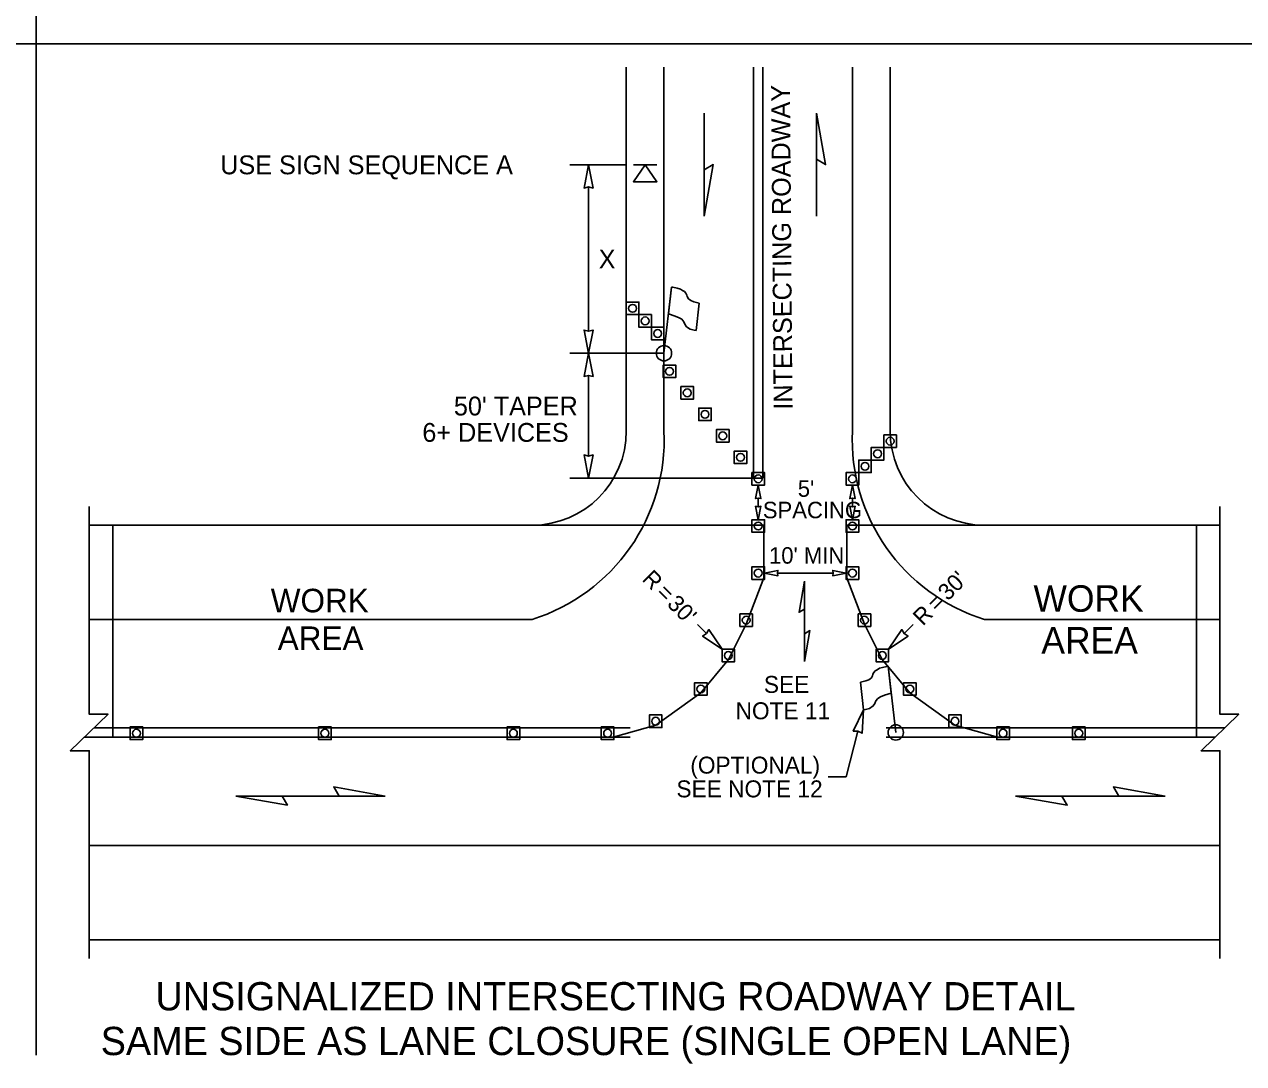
# Model space of a CAD drawing. Extents: x 99999.1 to 100095.7, y 99995 to 100010.7.
# Drawn here: x 100025.2 to 100030.38, y 100001.65 to 100006.06 of the extents above; entities that cross this region are included whole.
import ezdxf

# ---------------------------------------------------------------- set-up
doc = ezdxf.new("R2010")
doc.units = 0
for name, color, linetype in [('RD_ED_ShoulderPavedEdge', 7, 'Continuous'), ('RD_MK_LineDblYellowCenter', 7, 'Continuous'), ('RD_MK_LineEdgeWhite', 7, 'Continuous'), ('RD_MK_LineStop', 7, 'Continuous'), ('SH_DE_DetailBody1Text', 7, 'Continuous'), ('SH_DE_DetailHeading2Text', 7, 'Continuous'), ('TR_WZ_FlaggingStation', 7, 'Continuous'), ('TR_WZ_PortableSignMountBlk-Org', 7, 'Continuous'), ('TR_WZ_TrafficCone', 7, 'Continuous'), ('TR_WZ_WorkAreaLabel', 7, 'Continuous'), ('TR_WZ_WorkZoneDetails', 7, 'Continuous'), ('TR_WZ_WorkZoneTextCurrent', 7, 'Continuous')]:
    doc.layers.add(name, color=color, linetype=linetype)

msp = doc.modelspace()

# ---------------------------------------------------------------- linework, layer by layer
at = {"layer": 'RD_ED_ShoulderPavedEdge'}
for p, q in [((100025.475, 100003.9359), (100027.355, 100003.9359)), ((100029.275, 100003.9359), (100030.275, 100003.9359)), ((100025.475, 100002.1759), (100030.275, 100002.1759))]:
    msp.add_line(p, q, dxfattribs=at)
for points in [[(100027.755, 100005.8804), (100027.755, 100004.3359)], [(100028.875, 100005.8804), (100028.875, 100004.3359)]]:
    msp.add_lwpolyline(points, dxfattribs=at)
for centre, start, end in [((100027.355, 100004.3359), 270, 0), ((100029.275, 100004.3359), 180, 270)]:
    msp.add_arc(centre, 0.4, start, end, dxfattribs=at)
at = {"layer": 'RD_MK_LineDblYellowCenter'}
for p, q in [((100028.295, 100005.8804), (100028.295, 100004.1359)), ((100028.335, 100005.8804), (100028.335, 100004.1359)), ((100025.4957, 100003.0759), (100027.7712, 100003.0759)), ((100028.8588, 100003.0759), (100030.2957, 100003.0759)), ((100025.4543, 100003.0359), (100027.7712, 100003.0359)), ((100028.8588, 100003.0359), (100030.2543, 100003.0359))]:
    msp.add_line(p, q, dxfattribs=at)
at = {"layer": 'RD_MK_LineEdgeWhite'}
for p, q in [((100027.915, 100004.3359), (100027.915, 100005.8804)), ((100028.715, 100004.3359), (100028.715, 100005.8804)), ((100025.475, 100003.5359), (100027.355, 100003.5359)), ((100029.275, 100003.5359), (100030.275, 100003.5359)), ((100025.475, 100002.5759), (100030.275, 100002.5759))]:
    msp.add_line(p, q, dxfattribs=at)
for centre, start, end in [((100027.1158, 100004.2993), 287.3948, 2.6212), ((100029.5142, 100004.2993), 177.3788, 252.6052)]:
    msp.add_arc(centre, 0.8, start, end, dxfattribs=at)
at = {"layer": 'RD_MK_LineStop'}
msp.add_line((100027.899, 100004.1359), (100028.335, 100004.1359), dxfattribs=at)
at = {"layer": 'TR_WZ_FlaggingStation'}
for p, q in [((100027.915, 100004.6659), (100027.9471, 100004.9468)), ((100027.934, 100004.8328), (100027.9471, 100004.9471)), ((100028.065, 100004.8793), (100028.0517, 100004.7621)), ((100027.934, 100004.8328), (100027.934, 100004.8328)), ((100028.8797, 100003.2228), (100028.8667, 100003.3371)), ((100028.8988, 100003.0559), (100028.8667, 100003.3368)), ((100028.7487, 100003.2693), (100028.762, 100003.1521)), ((100028.8797, 100003.2228), (100028.8797, 100003.2228))]:
    msp.add_line(p, q, dxfattribs=at)
for points in [[(100027.9471, 100004.9471), (100027.9528, 100004.9459), (100027.9707, 100004.9424), (100027.9845, 100004.9383), (100027.9942, 100004.9322), (100028.0027, 100004.9275), (100028.0084, 100004.9206), (100028.0126, 100004.9128), (100028.0131, 100004.9066), (100028.0185, 100004.8974), (100028.0293, 100004.8899), (100028.0417, 100004.8847), (100028.065, 100004.8793)], [(100028.0517, 100004.7621), (100028.0436, 100004.7636), (100028.0259, 100004.7682), (100028.0103, 100004.7787), (100028.0037, 100004.7893), (100027.9998, 100004.7996), (100027.9907, 100004.8105), (100027.9798, 100004.8167), (100027.9624, 100004.8238), (100027.934, 100004.8328)], [(100028.8667, 100003.3371), (100028.8609, 100003.3359), (100028.8431, 100003.3324), (100028.8293, 100003.3283), (100028.8196, 100003.3222), (100028.8111, 100003.3175), (100028.8054, 100003.3106), (100028.8012, 100003.3028), (100028.8006, 100003.2966), (100028.7953, 100003.2874), (100028.7845, 100003.2799), (100028.7721, 100003.2747), (100028.7487, 100003.2693)], [(100028.762, 100003.1521), (100028.7702, 100003.1536), (100028.7879, 100003.1582), (100028.8035, 100003.1687), (100028.81, 100003.1793), (100028.814, 100003.1896), (100028.823, 100003.2005), (100028.834, 100003.2067), (100028.8514, 100003.2138), (100028.8797, 100003.2228)]]:
    msp.add_lwpolyline(points, dxfattribs=at)
for centre in [(100027.915, 100004.6659), (100028.8988, 100003.0559)]:
    msp.add_circle(centre, 0.0325, dxfattribs=at)
at = {"layer": 'TR_WZ_PortableSignMountBlk-Org'}
msp.add_line((100027.785, 100005.4659), (100027.885, 100005.4659), dxfattribs=at)
msp.add_lwpolyline([(100027.8349, 100005.4659), (100027.885, 100005.3941), (100027.785, 100005.3941)], close=True, dxfattribs=at)
at = {"layer": 'TR_WZ_TrafficCone'}
for points in [[(100027.8083, 100004.8833), (100027.8083, 100004.8299), (100027.755, 100004.8299), (100027.755, 100004.8833), (100027.8083, 100004.8833)], [(100027.755, 100004.8833), (100027.755, 100004.8299), (100027.8083, 100004.8299), (100027.8083, 100004.8833), (100027.755, 100004.8833)], [(100027.8617, 100004.8299), (100027.8617, 100004.7766), (100027.8083, 100004.7766), (100027.8083, 100004.8299), (100027.8617, 100004.8299)], [(100027.8083, 100004.8299), (100027.8083, 100004.7766), (100027.8617, 100004.7766), (100027.8617, 100004.8299), (100027.8083, 100004.8299)], [(100027.915, 100004.7766), (100027.915, 100004.7233), (100027.8617, 100004.7233), (100027.8617, 100004.7766), (100027.915, 100004.7766)], [(100027.8617, 100004.7766), (100027.8617, 100004.7233), (100027.915, 100004.7233), (100027.915, 100004.7766), (100027.8617, 100004.7766)], [(100027.9117, 100004.6159), (100027.965, 100004.6159), (100027.965, 100004.5626), (100027.9117, 100004.5626), (100027.9117, 100004.6159)], [(100027.9117, 100004.5626), (100027.965, 100004.5626), (100027.965, 100004.6159), (100027.9117, 100004.6159), (100027.9117, 100004.5626)], [(100027.987, 100004.5246), (100028.0404, 100004.5246), (100028.0404, 100004.4712), (100027.987, 100004.4712), (100027.987, 100004.5246)], [(100027.987, 100004.4712), (100028.0404, 100004.4712), (100028.0404, 100004.5246), (100027.987, 100004.5246), (100027.987, 100004.4712)], [(100028.0624, 100004.4332), (100028.1157, 100004.4332), (100028.1157, 100004.3799), (100028.0624, 100004.3799), (100028.0624, 100004.4332)], [(100028.0624, 100004.3799), (100028.1157, 100004.3799), (100028.1157, 100004.4332), (100028.0624, 100004.4332), (100028.0624, 100004.3799)], [(100028.1377, 100004.3419), (100028.191, 100004.3419), (100028.191, 100004.2886), (100028.1377, 100004.2886), (100028.1377, 100004.3419)], [(100028.1377, 100004.2886), (100028.191, 100004.2886), (100028.191, 100004.3419), (100028.1377, 100004.3419), (100028.1377, 100004.2886)], [(100028.9016, 100004.3192), (100028.8483, 100004.3192), (100028.8483, 100004.2659), (100028.9016, 100004.2659), (100028.9016, 100004.3192)], [(100028.9016, 100004.2659), (100028.8483, 100004.2659), (100028.8483, 100004.3192), (100028.9016, 100004.3192), (100028.9016, 100004.2659)], [(100028.213, 100004.2506), (100028.2664, 100004.2506), (100028.2664, 100004.1972), (100028.213, 100004.1972), (100028.213, 100004.2506)], [(100028.213, 100004.1972), (100028.2664, 100004.1972), (100028.2664, 100004.2506), (100028.213, 100004.2506), (100028.213, 100004.1972)], [(100028.8483, 100004.2659), (100028.795, 100004.2659), (100028.795, 100004.2126), (100028.8483, 100004.2126), (100028.8483, 100004.2659)], [(100028.8483, 100004.2126), (100028.795, 100004.2126), (100028.795, 100004.2659), (100028.8483, 100004.2659), (100028.8483, 100004.2126)], [(100028.795, 100004.2126), (100028.7416, 100004.2126), (100028.7416, 100004.1592), (100028.795, 100004.1592), (100028.795, 100004.2126)], [(100028.795, 100004.1592), (100028.7416, 100004.1592), (100028.7416, 100004.2126), (100028.795, 100004.2126), (100028.795, 100004.1592)], [(100028.2884, 100004.1592), (100028.3417, 100004.1592), (100028.3417, 100004.1059), (100028.2884, 100004.1059), (100028.2884, 100004.1592)], [(100028.2884, 100004.1059), (100028.3417, 100004.1059), (100028.3417, 100004.1592), (100028.2884, 100004.1592), (100028.2884, 100004.1059)], [(100028.7416, 100004.1592), (100028.6883, 100004.1592), (100028.6883, 100004.1059), (100028.7416, 100004.1059), (100028.7416, 100004.1592)], [(100028.7416, 100004.1059), (100028.6883, 100004.1059), (100028.6883, 100004.1592), (100028.7416, 100004.1592), (100028.7416, 100004.1059)], [(100028.2884, 100003.9592), (100028.3417, 100003.9592), (100028.3417, 100003.9059), (100028.2884, 100003.9059), (100028.2884, 100003.9592)], [(100028.2884, 100003.9059), (100028.3417, 100003.9059), (100028.3417, 100003.9592), (100028.2884, 100003.9592), (100028.2884, 100003.9059)], [(100028.7416, 100003.9592), (100028.6883, 100003.9592), (100028.6883, 100003.9059), (100028.7416, 100003.9059), (100028.7416, 100003.9592)], [(100028.7416, 100003.9059), (100028.6883, 100003.9059), (100028.6883, 100003.9592), (100028.7416, 100003.9592), (100028.7416, 100003.9059)], [(100028.2884, 100003.7592), (100028.3417, 100003.7592), (100028.3417, 100003.7059), (100028.2884, 100003.7059), (100028.2884, 100003.7592)], [(100028.2884, 100003.7059), (100028.3417, 100003.7059), (100028.3417, 100003.7592), (100028.2884, 100003.7592), (100028.2884, 100003.7059)], [(100028.7416, 100003.7592), (100028.6883, 100003.7592), (100028.6883, 100003.7059), (100028.7416, 100003.7059), (100028.7416, 100003.7592)], [(100028.7416, 100003.7059), (100028.6883, 100003.7059), (100028.6883, 100003.7592), (100028.7416, 100003.7592), (100028.7416, 100003.7059)], [(100028.2373, 100003.5592), (100028.2907, 100003.5592), (100028.2907, 100003.5059), (100028.2373, 100003.5059), (100028.2373, 100003.5592)], [(100028.2373, 100003.5059), (100028.2907, 100003.5059), (100028.2907, 100003.5592), (100028.2373, 100003.5592), (100028.2373, 100003.5059)], [(100028.7927, 100003.5592), (100028.7393, 100003.5592), (100028.7393, 100003.5059), (100028.7927, 100003.5059), (100028.7927, 100003.5592)], [(100028.7927, 100003.5059), (100028.7393, 100003.5059), (100028.7393, 100003.5592), (100028.7927, 100003.5592), (100028.7927, 100003.5059)], [(100028.1617, 100003.4093), (100028.215, 100003.4093), (100028.215, 100003.3559), (100028.1617, 100003.3559), (100028.1617, 100003.4093)], [(100028.1617, 100003.3559), (100028.215, 100003.3559), (100028.215, 100003.4093), (100028.1617, 100003.4093), (100028.1617, 100003.3559)], [(100028.8683, 100003.4093), (100028.815, 100003.4093), (100028.815, 100003.3559), (100028.8683, 100003.3559), (100028.8683, 100003.4093)], [(100028.8683, 100003.3559), (100028.815, 100003.3559), (100028.815, 100003.4093), (100028.8683, 100003.4093), (100028.8683, 100003.3559)], [(100028.0447, 100003.267), (100028.0981, 100003.267), (100028.0981, 100003.2136), (100028.0447, 100003.2136), (100028.0447, 100003.267)], [(100028.0447, 100003.2136), (100028.0981, 100003.2136), (100028.0981, 100003.267), (100028.0447, 100003.267), (100028.0447, 100003.2136)], [(100028.9853, 100003.267), (100028.9319, 100003.267), (100028.9319, 100003.2136), (100028.9853, 100003.2136), (100028.9853, 100003.267)], [(100028.9853, 100003.2136), (100028.9319, 100003.2136), (100028.9319, 100003.267), (100028.9853, 100003.267), (100028.9853, 100003.2136)], [(100027.853, 100003.1302), (100027.9064, 100003.1302), (100027.9064, 100003.0768), (100027.853, 100003.0768), (100027.853, 100003.1302)], [(100027.853, 100003.0768), (100027.9064, 100003.0768), (100027.9064, 100003.1302), (100027.853, 100003.1302), (100027.853, 100003.0768)], [(100029.177, 100003.1302), (100029.1236, 100003.1302), (100029.1236, 100003.0768), (100029.177, 100003.0768), (100029.177, 100003.1302)], [(100029.177, 100003.0768), (100029.1236, 100003.0768), (100029.1236, 100003.1302), (100029.177, 100003.1302), (100029.177, 100003.0768)], [(100025.649, 100003.0792), (100025.7024, 100003.0792), (100025.7024, 100003.0259), (100025.649, 100003.0259), (100025.649, 100003.0792)], [(100025.649, 100003.0259), (100025.7024, 100003.0259), (100025.7024, 100003.0792), (100025.649, 100003.0792), (100025.649, 100003.0259)], [(100026.449, 100003.0792), (100026.5024, 100003.0792), (100026.5024, 100003.0259), (100026.449, 100003.0259), (100026.449, 100003.0792)], [(100026.449, 100003.0259), (100026.5024, 100003.0259), (100026.5024, 100003.0792), (100026.449, 100003.0792), (100026.449, 100003.0259)], [(100027.249, 100003.0792), (100027.3024, 100003.0792), (100027.3024, 100003.0259), (100027.249, 100003.0259), (100027.249, 100003.0792)], [(100027.249, 100003.0259), (100027.3024, 100003.0259), (100027.3024, 100003.0792), (100027.249, 100003.0792), (100027.249, 100003.0259)], [(100027.649, 100003.0792), (100027.7024, 100003.0792), (100027.7024, 100003.0259), (100027.649, 100003.0259), (100027.649, 100003.0792)], [(100027.649, 100003.0259), (100027.7024, 100003.0259), (100027.7024, 100003.0792), (100027.649, 100003.0792), (100027.649, 100003.0259)], [(100029.381, 100003.0792), (100029.3276, 100003.0792), (100029.3276, 100003.0259), (100029.381, 100003.0259), (100029.381, 100003.0792)], [(100029.381, 100003.0259), (100029.3276, 100003.0259), (100029.3276, 100003.0792), (100029.381, 100003.0792), (100029.381, 100003.0259)], [(100029.649, 100003.0792), (100029.7024, 100003.0792), (100029.7024, 100003.0259), (100029.649, 100003.0259), (100029.649, 100003.0792)], [(100029.649, 100003.0259), (100029.7024, 100003.0259), (100029.7024, 100003.0792), (100029.649, 100003.0792), (100029.649, 100003.0259)]]:
    msp.add_lwpolyline(points, dxfattribs=at)
for centre in [(100027.7817, 100004.8566), (100027.835, 100004.8033), (100027.8883, 100004.7499), (100027.9384, 100004.5892), (100028.0137, 100004.4979), (100028.089, 100004.4066), (100028.1644, 100004.3152), (100028.875, 100004.2926), (100028.8216, 100004.2392), (100028.2397, 100004.2239), (100028.7683, 100004.1859), (100028.315, 100004.1326), (100028.715, 100004.1326), (100028.315, 100003.9326), (100028.715, 100003.9326), (100028.315, 100003.7326), (100028.715, 100003.7326), (100028.264, 100003.5326), (100028.766, 100003.5326), (100028.1883, 100003.3826), (100028.8417, 100003.3826), (100028.0714, 100003.2403), (100028.9586, 100003.2403), (100027.8797, 100003.1035), (100029.1503, 100003.1035), (100025.6757, 100003.0526), (100026.4757, 100003.0526), (100027.2757, 100003.0526), (100027.6757, 100003.0526), (100029.3543, 100003.0526), (100029.6757, 100003.0526)]:
    msp.add_circle(centre, 0.0167, dxfattribs=at)
at = {"layer": 'TR_WZ_WorkZoneDetails'}
for p, q in [((100025.25, 100010.275), (100025.25, 100001.6859)), ((100025.25, 100005.9804), (100020, 100005.9804)), ((100030.5, 100005.9804), (100025.25, 100005.9804)), ((100028.0855, 100005.4448), (100028.0855, 100005.6859)), ((100027.755, 100005.4659), (100027.515, 100005.4659)), ((100028.5627, 100005.4894), (100028.5627, 100005.2483)), ((100027.595, 100004.7596), (100027.595, 100005.3722)), ((100027.915, 100004.6659), (100027.515, 100004.6659)), ((100027.595, 100004.2296), (100027.595, 100004.5722)), ((100027.899, 100004.1359), (100027.515, 100004.1359)), ((100028.315, 100004.0514), (100028.315, 100004.0137)), ((100028.715, 100004.0514), (100028.715, 100004.0137)), ((100028.6338, 100003.7326), (100028.3962, 100003.7326)), ((100028.5115, 100003.4752), (100028.5115, 100003.6199)), ((100028.5115, 100003.5799), (100028.5115, 100003.4352)), ((100028.0954, 100003.4755), (100028.057, 100003.514)), ((100028.9346, 100003.4755), (100028.973, 100003.514)), ((100028.7385, 100003.0614), (100028.688, 100002.8668)), ((100028.6118, 100002.8668), (100028.688, 100002.8668)), ((100026.2944, 100002.7859), (100026.5356, 100002.7859)), ((100026.5356, 100002.7859), (100026.2944, 100002.7859)), ((100029.6043, 100002.7859), (100029.8454, 100002.7859)), ((100029.8454, 100002.7859), (100029.6043, 100002.7859))]:
    msp.add_line(p, q, dxfattribs=at)
for points in [[(100028.5627, 100005.6859), (100028.6013, 100005.4671), (100028.5627, 100005.4894)], [(100027.595, 100005.4659), (100027.6143, 100005.3676), (100027.595, 100005.3722), (100027.5757, 100005.3676)], [(100028.0855, 100005.2483), (100028.124, 100005.4671), (100028.0855, 100005.4448)], [(100027.595, 100004.6659), (100027.6143, 100004.7642), (100027.595, 100004.7596), (100027.5757, 100004.7642)], [(100027.595, 100004.6659), (100027.6143, 100004.5676), (100027.595, 100004.5722), (100027.5757, 100004.5676)], [(100027.595, 100004.1359), (100027.6143, 100004.2342), (100027.595, 100004.2296), (100027.5757, 100004.2342)], [(100028.315, 100004.1059), (100028.3262, 100004.0487), (100028.315, 100004.0514), (100028.3038, 100004.0487)], [(100028.7149, 100004.1059), (100028.7261, 100004.0487), (100028.7149, 100004.0514), (100028.7037, 100004.0487)], [(100028.315, 100003.9592), (100028.3263, 100004.0164), (100028.315, 100004.0137), (100028.3038, 100004.0164)], [(100028.715, 100003.9592), (100028.7262, 100004.0164), (100028.715, 100004.0137), (100028.7037, 100004.0164)], [(100028.3383, 100003.9359), (100028.3383, 100003.7126), (100028.264, 100003.5159), (100028.1883, 100003.3659), (100028.1883, 100003.3659), (100028.1883, 100003.3659), (100028.0714, 100003.2236), (100028.0714, 100003.2236), (100028.0714, 100003.2236), (100027.8797, 100003.0868), (100027.699, 100003.0359), (100026.499, 100003.0359), (100025.699, 100003.0359), (100025.575, 100003.0359), (100025.575, 100003.9359)], [(100030.175, 100003.9359), (100030.175, 100003.0359), (100029.699, 100003.0359), (100029.6523, 100003.0359), (100029.6523, 100003.0359), (100029.6523, 100003.0359), (100029.331, 100003.0359), (100029.331, 100003.0359), (100029.331, 100003.0359), (100029.1503, 100003.0868), (100028.9586, 100003.2236), (100028.8417, 100003.3659), (100028.766, 100003.5159), (100028.6917, 100003.7126), (100028.6917, 100003.9359)], [(100028.3417, 100003.7326), (100028.3989, 100003.7214), (100028.3962, 100003.7326), (100028.3989, 100003.7438)], [(100028.6883, 100003.7326), (100028.6311, 100003.7214), (100028.6338, 100003.7326), (100028.6311, 100003.7438)], [(100028.5115, 100003.6978), (100028.4883, 100003.5665), (100028.5115, 100003.5799)], [(100028.1617, 100003.4093), (100028.0786, 100003.4652), (100028.0954, 100003.4756), (100028.1058, 100003.4924)], [(100028.5115, 100003.3573), (100028.5346, 100003.4886), (100028.5115, 100003.4752)], [(100028.8683, 100003.4093), (100028.9514, 100003.4652), (100028.9346, 100003.4756), (100028.9242, 100003.4924)], [(100028.762, 100003.1521), (100028.7187, 100003.0618), (100028.7385, 100003.0614), (100028.7561, 100003.0522)], [(100026.7321, 100002.7859), (100026.5133, 100002.8245), (100026.5356, 100002.7859)], [(100030.0419, 100002.7859), (100029.8231, 100002.8245), (100029.8454, 100002.7859)], [(100026.0979, 100002.7859), (100026.3167, 100002.7473), (100026.2944, 100002.7859)], [(100029.4077, 100002.7859), (100029.6265, 100002.7473), (100029.6043, 100002.7859)]]:
    msp.add_lwpolyline(points, close=True, dxfattribs=at)
for points in [[(100025.475, 100002.0959), (100025.475, 100002.9785), (100025.395, 100002.9785), (100025.555, 100003.1333), (100025.475, 100003.1333), (100025.475, 100004.0159)], [(100030.275, 100002.0959), (100030.275, 100002.9785), (100030.195, 100002.9785), (100030.355, 100003.1333), (100030.275, 100003.1333), (100030.275, 100004.0159)]]:
    msp.add_lwpolyline(points, dxfattribs=at)

# ---------------------------------------------------------------- texts
at = {"layer": 'SH_DE_DetailBody1Text'}
msp.add_text('INTERSECTING ROADWAY', height=0.08, rotation=90.4626, dxfattribs=at).set_placement((100028.4607, 100004.4269))
at = {"layer": 'SH_DE_DetailHeading2Text'}
for s, p in [('UNSIGNALIZED INTERSECTING ROADWAY DETAIL', (100025.7563, 100001.8759)), ('SAME SIDE AS LANE CLOSURE (SINGLE OPEN LANE)', (100025.524, 100001.6859))]:
    msp.add_text(s, height=0.12, rotation=360, dxfattribs=at).set_placement(p)
at = {"layer": 'TR_WZ_WorkAreaLabel'}
for s, p in [('WORK', (100026.2458, 100003.5659)), ('AREA', (100026.2754, 100003.4059))]:
    msp.add_text(s, height=0.1, dxfattribs=at).set_placement(p)
at = {"layer": 'TR_WZ_WorkZoneDetails'}
for s, p in [('WORK', (100029.4835, 100003.5683)), ('AREA', (100029.5168, 100003.391))]:
    msp.add_text(s, height=0.1125, dxfattribs=at).set_placement(p)
at = {"layer": 'TR_WZ_WorkZoneTextCurrent'}
for s, height, p in [('USE SIGN SEQUENCE A', 0.08, (100026.0313, 100005.4259)), ('X', 0.08, (100027.6379, 100005.0259)), ("50' TAPER", 0.08, (100027.0232, 100004.4019)), ('6+ DEVICES', 0.08, (100026.8892, 100004.2899)), ("5'", 0.07, (100028.483, 100004.0564)), ('SPACING', 0.07, (100028.3346, 100003.9654)), ("10' MIN", 0.07, (100028.3608, 100003.7726)), ('SEE', 0.072, (100028.3391, 100003.2239)), ('NOTE 11', 0.072, (100028.2189, 100003.1119)), ('(OPTIONAL)', 0.072, (100028.0267, 100002.8812)), ('SEE NOTE 12', 0.072, (100027.9678, 100002.7804))]:
    msp.add_text(s, height=height, dxfattribs=at).set_placement(p)
for s, rotation, p in [('R', 315, (100027.8182, 100003.7032)), ("30'", 45, (100029.1202, 100003.6116)), ('=', 315, (100027.8774, 100003.644)), ("30'", 315, (100027.9242, 100003.5972)), ('=', 45, (100029.0734, 100003.5648)), ('R', 45, (100029.0142, 100003.5056))]:
    msp.add_text(s, height=0.07, rotation=rotation, dxfattribs=at).set_placement(p)

doc.saveas('drawing.dxf')
